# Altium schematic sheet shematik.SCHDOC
size A
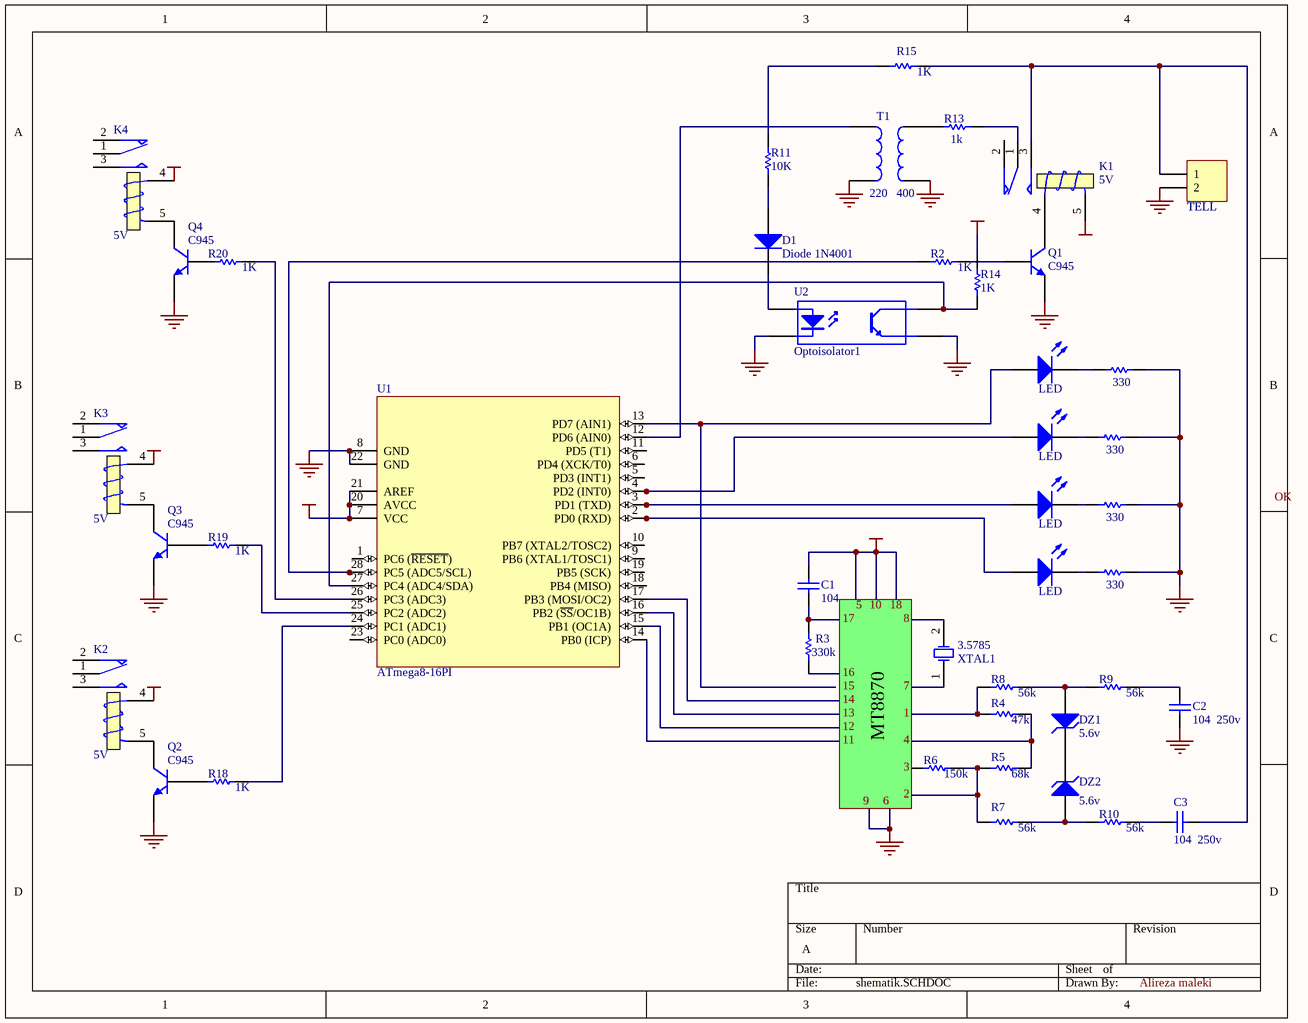
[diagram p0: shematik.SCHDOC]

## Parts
(Parts that share a designator on the sheet are numbered #1, #2 ... from top to bottom, then left to right.)
?#1  TELL  [HDR1X2]
?#2  LED  [LED-1]
?#3  value 330  [AXIAL-0.3]
?#4  LED  [LED-1]
?#5  value 330  [AXIAL-0.3]
?#6  LED  [LED-1]
?#7  value 330  [AXIAL-0.3]
?#8  LED  [LED-1]
?#9  value 330  [AXIAL-0.3]
C1  value 104  [CAPR2.54-5.1X3.2]
C2  value 104  250v  [CAPR2.54-5.1X3.2]
C3  value 104  250v  [CAPR2.54-5.1X3.2]
D1  Diode 1N4001  [DIO7.1-3.9x1.9]
DZ1  5.6v  [DIODE-0.7]
DZ2  5.6v  [DIODE-0.7]
K1  5V  [DIP-P5/X1.65]
K2  5V  [DIP-P5/X1.65]
K3  5V  [DIP-P5/X1.65]
K4  5V  [DIP-P5/X1.65]
Q1  C945  [BCY-W3/E4]
Q2  C945  [BCY-W3/E4]
Q3  C945  [BCY-W3/E4]
Q4  C945  [BCY-W3/E4]
R2  value 1K  [AXIAL-0.3]
R3  value 330k  [AXIAL-0.3]
R4  value 47k  [AXIAL-0.3]
R5  value 68k  [AXIAL-0.3]
R6  value 150k  [AXIAL-0.3]
R7  value 56k  [AXIAL-0.3]
R8  value 56k  [AXIAL-0.3]
R9  value 56k  [AXIAL-0.3]
R10  value 56k  [AXIAL-0.3]
R11  value 10K  [AXIAL-0.3]
R13  value 1k  [AXIAL-0.3]
R14  value 1K  [AXIAL-0.3]
R15  value 1K  [AXIAL-0.3]
R18  value 1K  [AXIAL-0.3]
R19  value 1K  [AXIAL-0.3]
R20  value 1K  [AXIAL-0.3]
T1  220   400  [TRANS]
U1  ATmega8-16PI  [28P3]
U2  Optoisolator1  [DIP-4]
XTAL1  3.5785  [BCY-W2/D3.1]

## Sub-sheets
? = MT8870: no entries
? = ?: no entries

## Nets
+5: K1.5(T2) R14.2
+5v: C1.1 K2.4(T1) K3.4(T1) K4.4(T1) U1.7(VCC) U1.20(AVCC) U1.21(AREF)
GND: ?#1.2 ?#3.2 ?#5.2 ?#7.2 ?#9.2 C2.2 Q1.1(E) Q2.1(E) Q3.1(E) Q4.1(E) T1.2 T1.4 U1.8(GND) U1.22(GND) U2.2(K) U2.4(E)
14: U1.16(PB2_(~{SS}/OC1B)) U1.17(PB3_(MOSI/OC2))
Net?#1_1: ?#1.1 C3.2 K1.3(NO) R15.2
Net?#2_1: ?#2.1(A) U1.13(PD7_(AIN1))
Net?#2_2: ?#2.2(K) ?#3.1
Net?#4_1: ?#4.1(A) U1.4(PD2_(INT0))
Net?#4_2: ?#4.2(K) ?#5.1
Net?#6_1: ?#6.1(A) U1.3(PD1_(TXD))
Net?#6_2: ?#6.2(K) ?#7.1
Net?#8_1: ?#8.1(A) U1.2(PD0_(RXD))
Net?#8_2: ?#8.2(K) ?#9.1
NetC1_2: C1.2 R3.2
NetC2_1: C2.1 R9.2
NetC3_1: C3.1 R10.2
NetD1_1: D1.1(A) R11.1
NetD1_2: D1.2(K) U2.1(A)
NetDZ1_1: DZ1.1(A) R8.2 R9.1
NetDZ1_2: DZ1.2(K) DZ2.2(K)
NetDZ2_1: DZ2.1(A) R7.2 R10.1
NetK1_1: K1.1(COM) R13.2
NetK1_4: K1.4(T1) Q1.3(C)
NetK2_5: K2.5(T2) Q2.3(C)
NetK3_5: K3.5(T2) Q3.3(C)
NetK4_5: K4.5(T2) Q4.3(C)
NetQ1_2: Q1.2(B) R2.2
NetQ2_2: Q2.2(B) R18.1
NetQ3_2: Q3.2(B) R19.1
NetR2_1: R2.1 U1.28(PC5_(ADC5/SCL))
NetR4_1: R4.1 R5.1
NetR4_2: R4.2 R8.1
NetR5_2: R5.2 R6.2 R7.1
NetR11_2: R11.2 R15.1
NetR13_1: R13.1 T1.3
NetR14_1: R14.1 U1.27(PC4_(ADC4/SDA)) U2.3(C)
NetR18_2: R18.2 U1.24(PC1_(ADC1))
NetR19_2: R19.2 U1.25(PC2_(ADC2))
NetR20_2: R20.2 U1.26(PC3_(ADC3))
NetT1_1: T1.1 U1.12(PD6_(AIN0))

Not connected (* = marked no-connect by the designer): K1 2(NC); K2 1(COM) 2(NC) 3(NO); K3 1(COM) 2(NC) 3(NO); K4 1(COM) 2(NC) 3(NO); Q4 2(B); R3 1; R6 1; R20 1; U1 1(PC6_(~{RESET}))* 5(PD3_(INT1))* 6(PD4_(XCK/T0))* 9(PB6_(XTAL1/TOSC1))* 10(PB7_(XTAL2/TOSC2))* 11(PD5_(T1)) 14(PB0_(ICP)) 15(PB1_(OC1A)) 18(PB4_(MISO)) 19(PB5_(SCK))* 23(PC0_(ADC0)); XTAL1 1(OSC1) 2(OSC2)

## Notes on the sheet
- Labels drawn without touching a wire or pin: 1, 2, 3, 4, 5, 6, 7, 8, 9, 10, 11, 12, 13, 15, 16, 17, 18, Alireza maleki, OK

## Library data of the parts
?#1 = Header 2: Header, 2-Pin
?#2 ?#4 ?#6 ?#8 = LED1: Typical RED GaAs LED
?#3 ?#5 ?#7 ?#9 R2-R11 R13-R15 R18-R20 = Res1: Resistor
C1-C3 = Cap: Capacitor
D1 = Diode 1N914: High Conductance Fast Diode; Revision 1: 11-Jul-2000: SIM Model Added.; Revision 2: 17-Jul-2002: Re-released for DXP Platform.; Code - JEDEC: DO-204-AH
DZ1 DZ2 = D Zener: Zener Diode
K1-K4 = Relay: SPDT Relay
Q1-Q4 = 2N3904: NPN General Purpose Amplifier; Revision 1: 11-Jul-2000: SIM Model Added.; Revision 2: 17-Jul-2002: Re-released for DXP Platform.; Revision 3: 15-Jan-2003: PCB Footprint 'BCY-W3/D4.7' replaced; Code - JEDEC: TO-92A
T1 = Trans: Transformer
U1 = ATmega8-16PI: 8-Bit AVR Microcontroller with 8K Bytes of In-System Programmable Flash Memory; Package Information: Latest Revision: revB, Sep-2001
U2 = Optoisolator1: Optoisolator
XTAL1 = XTAL: Crystal Oscillator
